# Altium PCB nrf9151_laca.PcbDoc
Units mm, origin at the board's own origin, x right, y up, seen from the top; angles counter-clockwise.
Board outline 17 x 22.5 mm, 4 copper layers (Top Layer, Mid-Layer 1, Mid-Layer 2, Bottom Layer), stack 1.514 mm thick; 12 components, 86 nets, 135 pads, 104 vias.
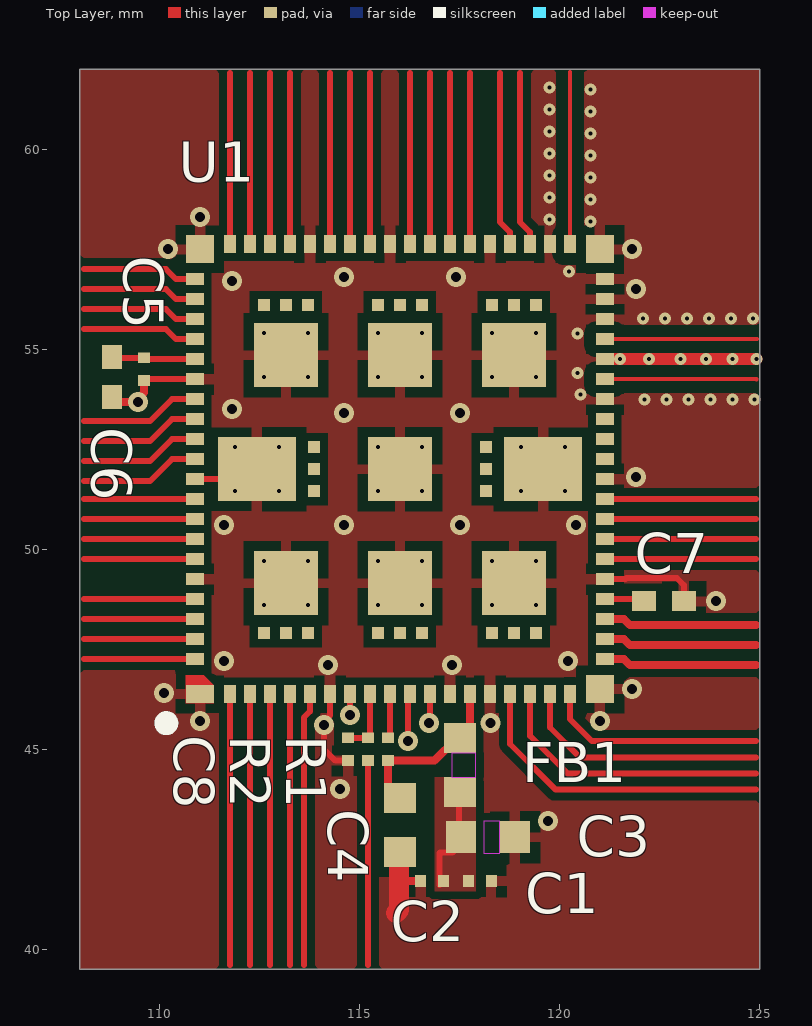
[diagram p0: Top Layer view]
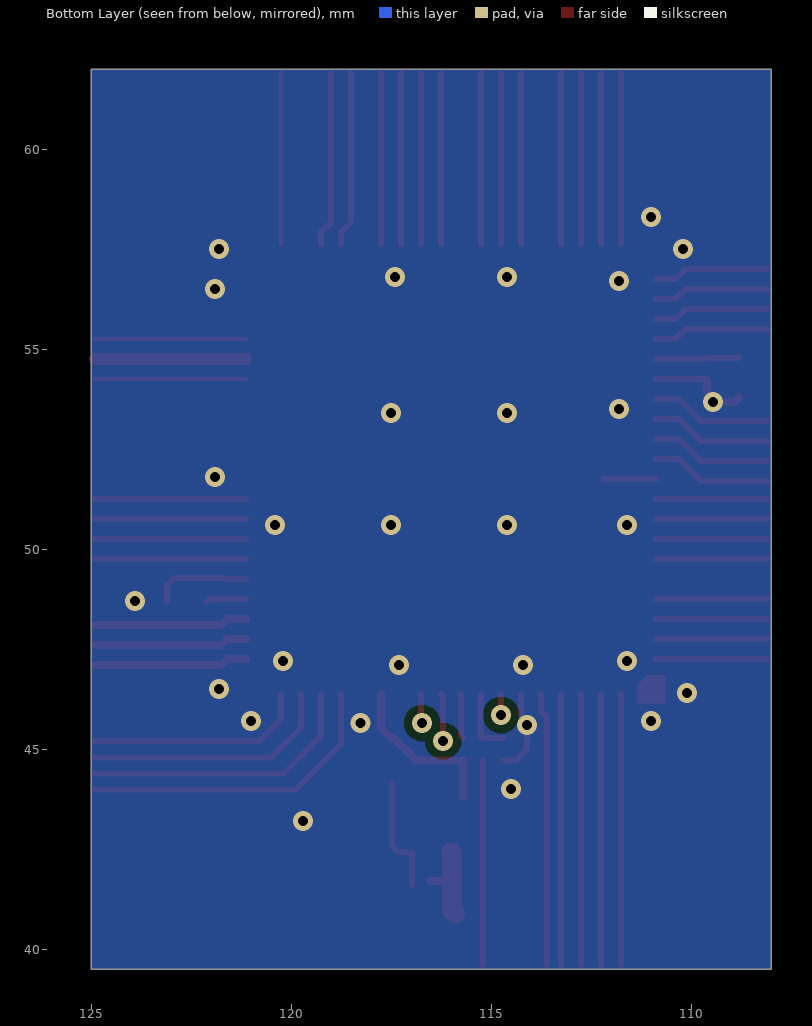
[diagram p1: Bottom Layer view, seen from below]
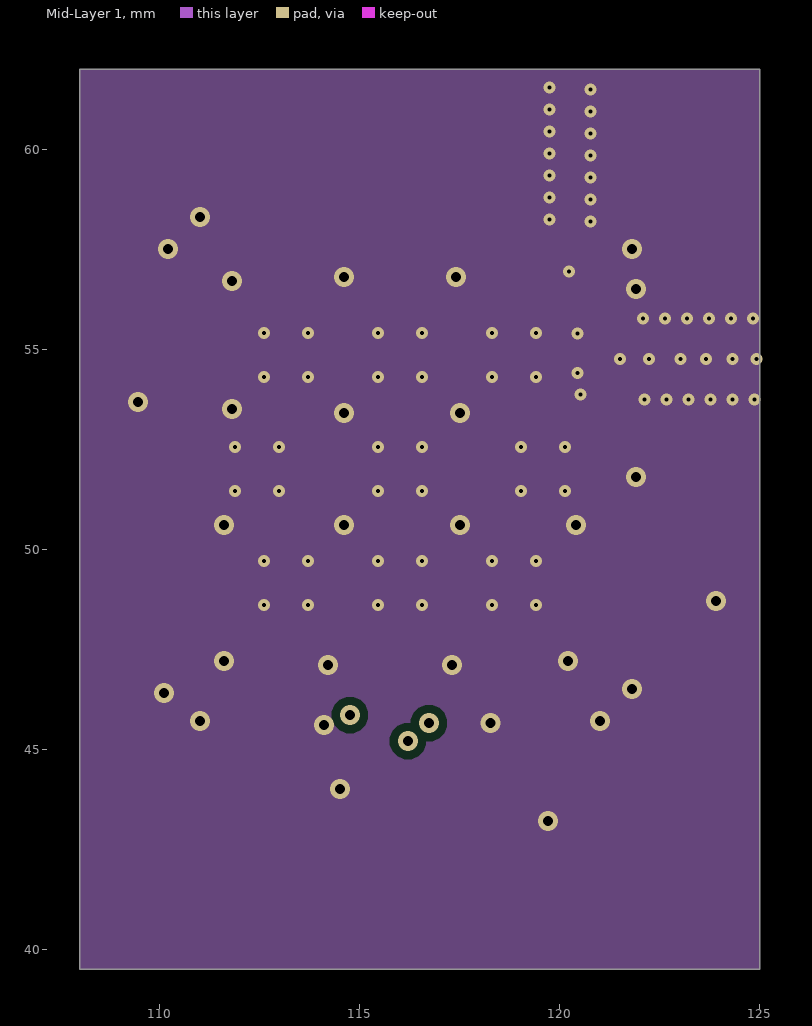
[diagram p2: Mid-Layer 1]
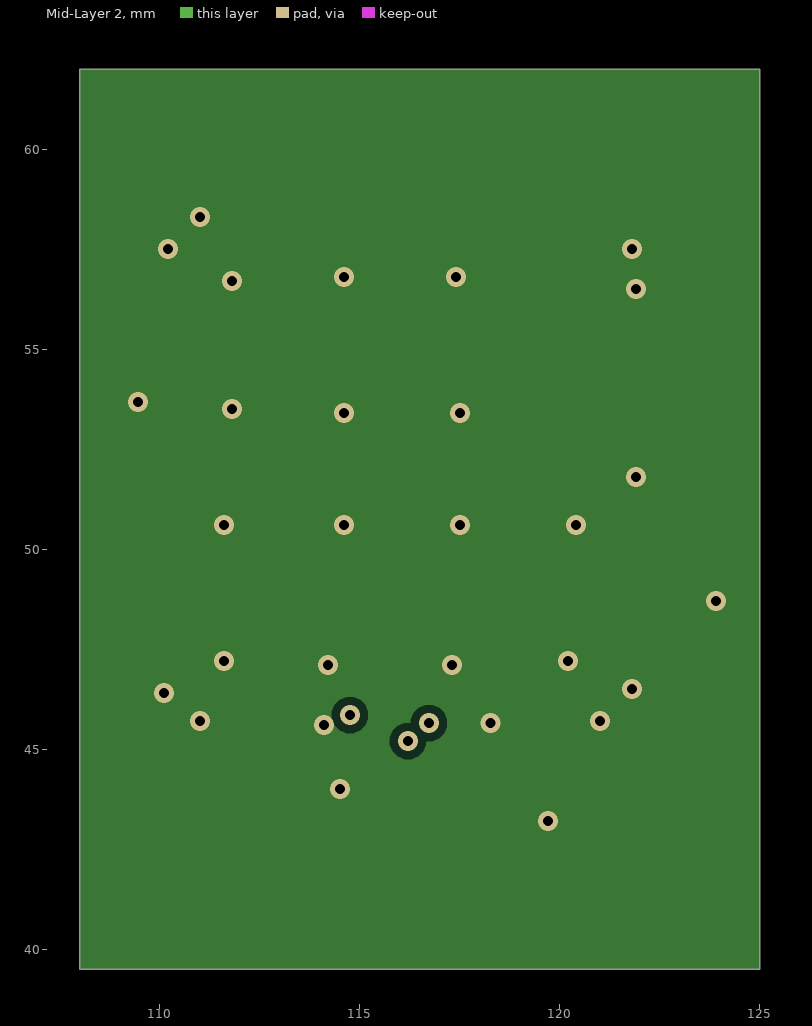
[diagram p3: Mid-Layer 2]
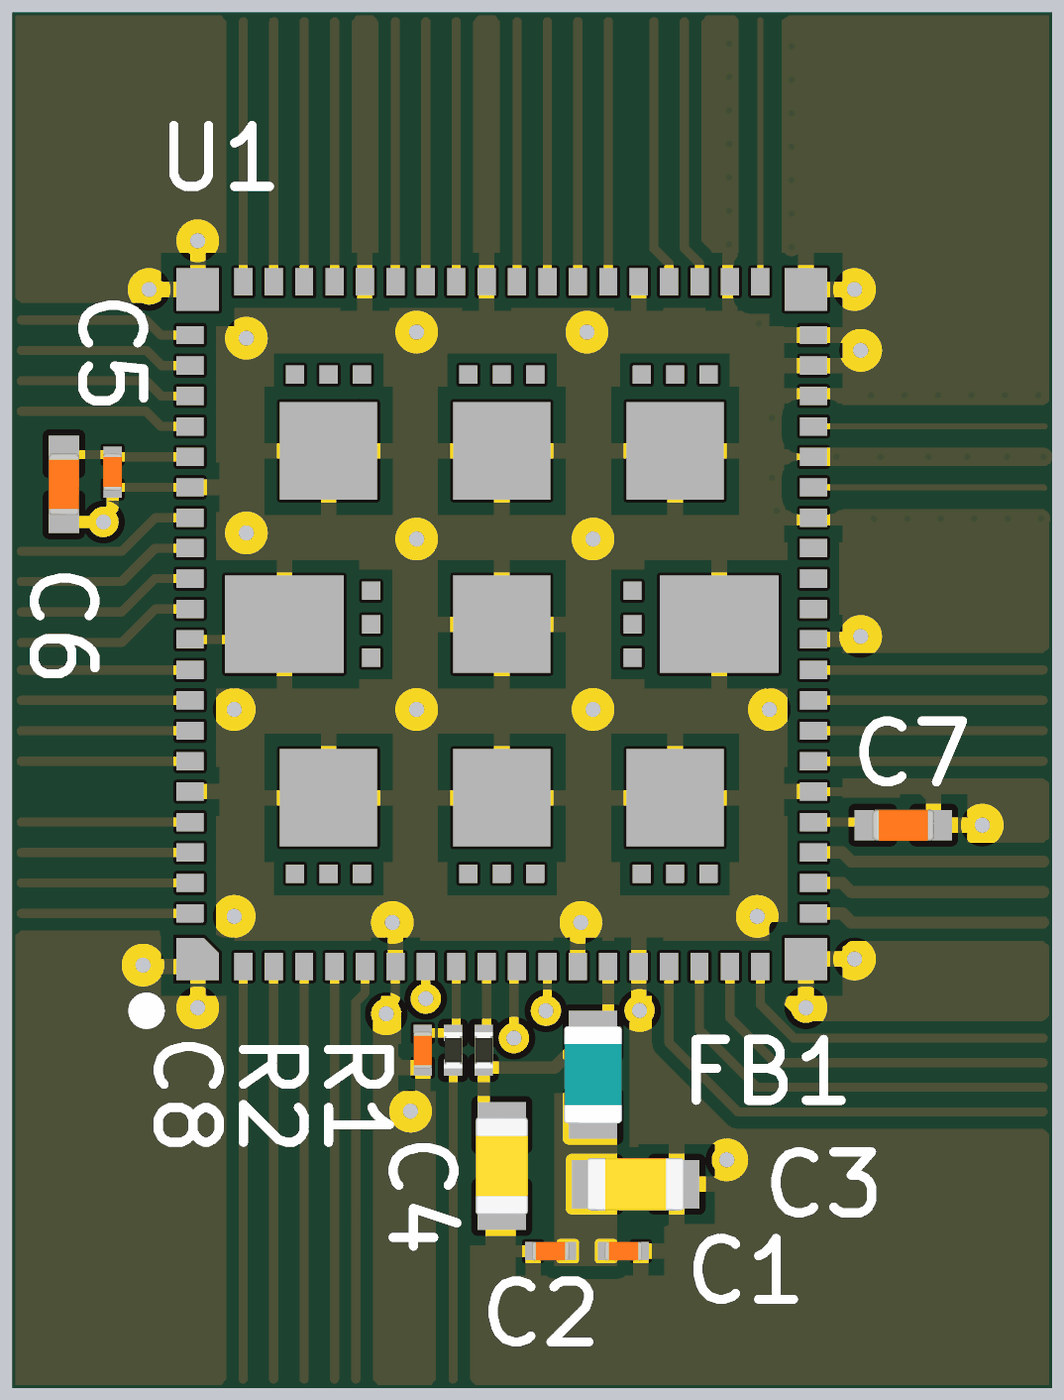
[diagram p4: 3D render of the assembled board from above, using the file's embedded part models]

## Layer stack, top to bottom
Top Solder: solder mask 0.05, Solder Resist Halogen-Free, Dk 3.5
Top Layer: signal copper 0.035
Dielectric1: prepreg 0.072, FR-4 Halogen-Free, Dk 4.18
Mid-Layer 1: signal copper 0.035
Dielectric2: core 1.23, FR-4 Halogen-Free, Dk 4.74
Mid-Layer 2: signal copper 0.035
Dielectric3: prepreg 0.072, FR-4 Halogen-Free, Dk 4.18
Bottom Layer: signal copper 0.035
Bottom Solder: solder mask 0.05, Solder Resist Halogen-Free, Dk 3.5

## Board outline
108,39.5 125,39.5 125,62 108,62

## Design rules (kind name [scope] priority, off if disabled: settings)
Clearance Clearance_1 [InNamedPolygon('Top_Layer-GND') or InNamedPolygon('Bottom_Layer-GND') or InNamedPolygon('Mid_Layer_1-GND') or InNamedPolygon('Mid_Layer_2-GND')] p1: gap=0.2 ignorepadtopadclearanceinfootprint=FALSE
Clearance GND_1 [InNet('GND')] p2: gap=0.15 ignorepadtopadclearanceinfootprint=FALSE except(0: Poly-Region)
Clearance [All] p3: gap=0.1 ignorepadtopadclearanceinfootprint=FALSE
MaxMinImpedance "Schematic Impedance Constraint_3" [InNetClass('50Ohm')] p1: minimum=50.00 maximum=50.00
PolygonConnect VDD_nRF [InNet('VDD_nRF')] p1: connectstyle=Direct reliefconductorwidth=0.254 reliefentries=4 polygonreliefangle="90 Angle" airgapwidth=0.254
PolygonConnect GND [IsPolygon vs IsVia] p2: connectstyle=Direct reliefconductorwidth=0.254 reliefentries=4 polygonreliefangle="90 Angle" airgapwidth=0.254
PolygonConnect [All] p3: connectstyle=Relief reliefconductorwidth=0.254 reliefentries=4 polygonreliefangle="90 Angle" airgapwidth=0.254
RoutingCorners [All] p1: cornerstyle=45-Degree minsetback=0.5 maxsetback=0.5
RoutingVias [All] p1: holewidth=0.25 width=0.5 viastyle="Through Hole" minholewidth=0.15 minwidth=0.3 maxholewidth=0.5 maxwidth=1
SolderMaskExpansion [All] p1: expansion=0.102 istentingtop=FALSE
Width RF_nets [InNetClass('50Ohm')] p1: maxlimit=0.254 minlimit=0.1 preferedwidth=0.254 toplayer_maxwidth=0.1 toplayer_prefwidth=0.1 bottomlayer_maxwidth=0.1 bottomlayer_prefwidth=0.1 impedanceprofiledriven=TRUE impedanceprofileid={14974C9B-F196-4B99-8CAC-E9FB9BDD5449} impedanceprofilevalue=50.000000 minimp=50.000000 maximp=50.000000 favimp=50.000000
Width "All tracks" [All] p2: maxlimit=1 minlimit=0.1 preferedwidth=0.15
29 further rules are at their usual default settings.

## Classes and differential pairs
net class 50Ohm: ANT AUX GPS

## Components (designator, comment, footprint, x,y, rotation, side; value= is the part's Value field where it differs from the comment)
C1 "1.0µF" CAPC0603X03L_C 118,41.7 r0 top
C2 "1.0µF" CAPC0603X03L_C 116.8,41.7 r180 top
C3 "10µF" CAPC1608X06L 118.2,42.8 r0 top
C4 "10µF" CAPC1608X06L 116,43.1 r270 top
C5 "100nF" CAPC0603X03L_C 109.6,54.5 r270 top
C6 "4.7µF" CAPC1005X04L 108.8,54.3 r270 top
C7 "4.7µF" CAPC1005X04L 122.6,48.7 r0 top
C8 "100nF" CAPC0603X03L_C 114.7,45 r270 top
FB1 "22R@100M/6A" INDC1608X06L 117.5,44.6 r90 top
R1 "10k" RESC0603X03L_C 115.7,45 r90 top
R2 "1k" RESC0603X03L_C 115.2,45 r90 top
U1 "nRF9151-LACAA0A" LGA50P1210X1110X130-113N 116,52 r0 top

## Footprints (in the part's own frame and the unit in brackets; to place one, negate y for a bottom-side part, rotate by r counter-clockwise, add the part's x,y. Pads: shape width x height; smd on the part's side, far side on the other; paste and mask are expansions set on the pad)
CAPC0603X03L_C [mm] "Chip Capacitor, 2-Leads, Body 0.6x0.3mm, IPC High Density"
  rect 0.27x0.3 smd mask+0.05: 1(-0.285,0) 2(0.285,0)
  body extent -0.3,-0.15 0.31,0.15, height 0.3
CAPC1005X04L [mm] "Chip Capacitor, 2-Leads, Body 1.0x0.5mm, IPC High Density"
  rect 0.6x0.5 smd: 1(-0.5,0) 2(0.5,0)
  body extent -0.51,-0.25 0.51,0.25, height 0.5
CAPC1608X06L [mm] "Chip Capacitor, 2-Leads, Body 1.6x0.8mm, IPC High Density"
  rect 0.75x0.8 smd: 1(-0.675,0) 2(0.675,0)
  body extent -0.8,-0.43 0.8,0.43, height 0.8
INDC1608X06L [mm] "Chip Inductor, 2-Leads, Body 1.6x0.8mm, IPC High Density"
  rect 0.75x0.8 smd: 1(-0.675,0) 2(0.675,0)
  body extent -0.8,-0.48 0.8,0.48, height 0.8
LGA50P1210X1110X130-113N [mm]
  rect 0.7x0.45 smd paste-2539.97 mask-5: 1(-5,-5.625)
  rect 0.3x0.45 smd mask+0.05: 2(-4.25,-5.625) 3(-3.75,-5.625) 4(-3.25,-5.625) 5(-2.75,-5.625) 6(-2.25,-5.625) 7(-1.75,-5.625) 8(-1.25,-5.625) 9(-0.75,-5.625) 10(-0.25,-5.625) 11(0.25,-5.625) 12(0.75,-5.625) 13(1.25,-5.625) 14(1.75,-5.625) 15(2.25,-5.625) 16(2.75,-5.625) 17(3.25,-5.625) 18(3.75,-5.625) 19(4.25,-5.625) 42(4.25,5.625) 43(3.75,5.625) 44(3.25,5.625) 45(2.75,5.625) 46(2.25,5.625) 47(1.75,5.625) 48(1.25,5.625) 49(0.75,5.625) 50(0.25,5.625) 51(-0.25,5.625) 52(-0.75,5.625) 53(-1.25,5.625) 54(-1.75,5.625) 55(-2.25,5.625) 56(-2.75,5.625) 57(-3.25,5.625) 58(-3.75,5.625) 59(-4.25,5.625)
  rect 0.7x0.7 smd mask+0.05: 20(5,-5.5) 41(5,5.5) 60(-5,5.5)
  rect 0.45x0.3 smd mask+0.05: 21(5.125,-4.75) 22(5.125,-4.25) 23(5.125,-3.75) 24(5.125,-3.25) 25(5.125,-2.75) 26(5.125,-2.25) 27(5.125,-1.75) 28(5.125,-1.25) 29(5.125,-0.75) 30(5.125,-0.25) 31(5.125,0.25) 32(5.125,0.75) 33(5.125,1.25) 34(5.125,1.75) 35(5.125,2.25) 36(5.125,2.75) 37(5.125,3.25) 38(5.125,3.75) 39(5.125,4.25) 40(5.125,4.75) 61(-5.125,4.75) 62(-5.125,4.25) 63(-5.125,3.75) 64(-5.125,3.25) 65(-5.125,2.75) 66(-5.125,2.25) 67(-5.125,1.75) 68(-5.125,1.25) 69(-5.125,0.75) 70(-5.125,0.25) 71(-5.125,-0.25) 72(-5.125,-0.75) 73(-5.125,-1.25) 74(-5.125,-1.75) 75(-5.125,-2.25) 76(-5.125,-2.75) 77(-5.125,-3.25) 78(-5.125,-3.75) 79(-5.125,-4.25) 80(-5.125,-4.75)
  rect 0.3x0.3 smd mask+0.05: 81(-3.4,-4.1) 82(-2.85,-4.1) 83(-2.3,-4.1) 84(-0.55,-4.1) 85(0,-4.1) 86(0.55,-4.1) 87(2.3,-4.1) 88(2.85,-4.1) 89(3.4,-4.1) 90(2.15,-0.55) 91(2.15,0) 92(2.15,0.55) 93(3.4,4.1) 94(2.85,4.1) 95(2.3,4.1) 96(0.55,4.1) 97(0,4.1) 98(-0.55,4.1) 99(-2.3,4.1) 100(-2.85,4.1) 101(-3.4,4.1) 102(-2.15,0.55) 103(-2.15,0) 104(-2.15,-0.55)
  rect 1.6x1.6 smd mask+0.05: 105(-2.85,-2.85) 106(0,-2.85) 107(2.85,-2.85) 109(2.85,2.85) 110(0,2.85) 111(-2.85,2.85) 113(0,0)
  rect 1.95x1.6 smd mask+0.05: 108(3.575,0) 112(-3.575,0)
  Top Layer region: -5.35,-5.15 -5.35,-5.85 -4.65,-5.85 -4.65,-5.4 -4.9,-5.15
  silkscreen extent -5.99,-6.5 -5.69,-6.2, body extent -5.6,-6.1 5.6,6.1, height 1.21
RESC0603X03L_C [mm] "Chip Resistor, 2-Leads, Body 0.6x0.3mm, IPC High Density"
  rect 0.27x0.3 smd: 1(-0.285,0) 2(0.285,0)
  body extent -0.3,-0.15 0.3,0.15, height 0.23

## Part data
C1 C2: library part C0201-1µ0-10V-X5R-GRM033R61A105ME15, "Capacitor, X5R, ±20%, 10V", Manufacturer=Murata, Manufacturer Part Number=GRM033R61A105ME15, Part number IPS=N.A., Part number NEMS=100200545, Supplier Part Number 1=490-13226-1-ND
C3 C4: library part C0603-10µ-10V-X6S-GRM188C81A106MA73, "Capacitor, Ceramic, 10µF 10V X6S 0603,±20%", Manufacturer=Murata, Manufacturer Part Number=GRM188C81A106MA73, Part number IPS=N.A., Part number NEMS=100200520, Supplier Part Number 1=490-7197-2-ND
C5: library part C0201-100n, "Capacitor, X5R, ±10%", Manufacturer=N.A., Part number IPS="00000001248, 00000002505", Part number NEMS=100200078, Part number Norautron=262071862
C6 C7: library part C0402-4µ7-10V-X5R, "Capacitor, X5R, 10V", Manufacturer=Murata, Manufacturer Part Number=GRM155R61A475MEAAD, Part number IPS=N.A., Part number NEMS=100200415, Supplier Part Number 1=490-14306-1-ND
C8: library part C0201-100n, "Capacitor, X5R, ±10%"
FB1: library part FB0603-22R@100MHz-6000mA, "Ferrite Bead, 22 Ohm @ 100MHz, 6000mA, 8 mOhm Max", Manufacturer=Murata, Manufacturer Part Number=BLM18SD220SN1D, Part number IPS=N.A., Supplier Part Number 1=490-15633-2-ND
R1: library part R0201-10k, "Resistor, ±1%, 0.05W", Manufacturer=N.A., Part number IPS=00000001255, Part number NEMS=100100065, Part number Norautron=26107101
R2: library part R0201-1k0, "Resistor, ±1%, 0.05W"
U1: "Low power System-in-Package with integrated LTE-M/NB-IoT modem and GPS", Manufacturer="Nordic Semiconductor", Part number IPS=N.A., Part number NEMS=102000328

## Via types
v1: diameter 0.3, hole 0.1, Top Layer to Mid-Layer 1, tented top, 36 vias
v2: diameter 0.3, hole 0.1, Top Layer to Mid-Layer 1, tented both sides, 36 vias
v3: diameter 0.5, hole 0.25, Top Layer to Bottom Layer, 32 vias

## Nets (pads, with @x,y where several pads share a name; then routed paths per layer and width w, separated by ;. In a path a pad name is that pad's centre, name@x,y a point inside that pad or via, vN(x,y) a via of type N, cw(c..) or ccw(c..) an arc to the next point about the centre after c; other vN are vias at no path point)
ANT: U1.35 | length 3.8
  Top Layer w0.1: U1.35 124.912,54.25 124.918,54.243
AUX: U1.37 | length 3.8
  Top Layer w0.1: U1.37 124.925,55.25
COEX0: U1.52 | length 4.3
  Top Layer w0.15: U1.52 115.25,61.9
COEX1: U1.53 | length 4.3
  Top Layer w0.15: U1.53 114.75,61.9
COEX2: U1.54 | length 4.3
  Top Layer w0.15: U1.54 114.25,61.9
DEC0: C7.1 U1.24 | length 1
  Top Layer w0.15: U1.24 122.05,48.75 C7.1
GND: C1.2 C2.2 C3.2 C4.2 C5.2 C6.2 C7.2 C8.2 U1.1 U1.7 U1.13 U1.15 U1.20 U1.25 U1.30 U1.34 U1.36 U1.38 U1.39 U1.40 U1.41 U1.43 U1.46 U1.51 U1.55 U1.60 U1.66 U1.71 U1.76 U1.105 U1.106 U1.107 U1.108 U1.109 U1.110 U1.111 U1.112 U1.113 | length 14.3
  Top Layer w0.15: C5.2@109.635,54.25 U1.66 ; U1.71 U1.112@112.175,51.75 ; U1.7 114.25,45.844 114.1,45.695 114.1,45 114.385,44.715 C8.2 ; U1.25 121.635,49.25 121.664,49.279 122.921,49.279 123.1,49.1 C7.2
  Top Layer w0.2: C6.2 108.92,53.68 v3(109.45,53.68) ; v3@109.45,53.682 109.45,53.761 109.6,53.911 C5.2 ; 115.98,41.7 C2.2
  Top Layer w0.3: U1.36 v1(124.907,54.75)
  Top Layer w0.5: 115.9,40.9 115.98,40.98 115.98,41.7 115.98,42.405 C4.2
  other v1: 122.117,53.737 122.667,53.737 123.217,53.737 123.767,53.737 124.317,53.737 124.867,53.737 120.518,53.862 120.443,54.407 121.501,54.75 122.227,54.75 123.016,54.75 123.653,54.75 124.307,54.75 120.441,55.391 122.072,55.763 122.622,55.763 123.172,55.763 123.722,55.763 124.272,55.763 124.822,55.763 120.229,56.941 120.763,58.195 119.737,58.241 120.763,58.745 119.737,58.791 120.763,59.295 119.737,59.341 120.763,59.845 119.737,59.891 120.763,60.395 119.737,60.441 120.763,60.945 119.737,60.991 120.763,61.495 119.737,61.541
  other v2: 112.6,48.6 113.7,48.6 115.45,48.6 116.55,48.6 118.3,48.6 119.4,48.6 112.6,49.7 113.7,49.7 115.45,49.7 116.55,49.7 118.3,49.7 119.4,49.7 111.875,51.45 112.975,51.45 115.45,51.45 116.55,51.45 119.025,51.45 120.125,51.45 111.875,52.55 112.975,52.55 115.45,52.55 116.55,52.55 119.025,52.55 120.125,52.55 112.6,54.3 113.7,54.3 115.45,54.3 116.55,54.3 118.3,54.3 119.4,54.3 112.6,55.4 113.7,55.4 115.45,55.4 116.55,55.4 118.3,55.4 119.4,55.4
  other v3: 119.7,43.2 114.5,44 114.1,45.6 118.265,45.655 111,45.7 121,45.7 110.1,46.4 121.8,46.5 114.2,47.1 117.3,47.1 111.6,47.2 120.2,47.2 123.9,48.7 111.6,50.6 114.6,50.6 117.5,50.6 120.4,50.6 121.9,51.8 114.6,53.4 117.5,53.4 111.8,53.5 121.9,56.5 111.8,56.7 114.6,56.8 117.4,56.8 110.2,57.5 121.8,57.5 111,58.3
GPS: U1.42 | length 4.3
  Top Layer w0.1: U1.42 120.25,61.925
MAGPIO0: U1.21 | length 3.8
  Top Layer w0.2: U1.21 121.6,47.25 121.75,47.1 124.9,47.1
MAGPIO1: U1.22 | length 3.8
  Top Layer w0.2: U1.22 121.6,47.75 121.75,47.6 124.9,47.6
MAGPIO2: U1.23 | length 3.8
  Top Layer w0.2: U1.23 121.6,48.25 121.75,48.1 124.9,48.1
MIPI_SCLK: U1.28 | length 3.8
  Top Layer w0.15: U1.28 124.9,50.75
MIPI_SDATA: U1.27 | length 3.8
  Top Layer w0.15: U1.27 124.9,50.25
MIPI_VIO: U1.29 | length 3.8
  Top Layer w0.15: U1.29 124.9,51.25
NetC4_1: C4.1 FB1.2 R1.1 U1.14 | length 4.1
  Top Layer w0.2: C4.1@115.697,43.815 115.7,43.818 R1.1 116.866,44.715 117.426,45.275 FB1.2 117.75,45.525 U1.14
NetC8_1: C8.1 R2.2 U1.9 | length 1.6
  Top Layer w0.15: C8.1 R2.2 115.25,45.335 U1.9
NetR1_2: R1.2 U1.10 | length 1.1
  Top Layer w0.15: R1.2 115.75,45.335 U1.10
NetU1_31: U1.31
NetU1_32: U1.32
NetU1_33: U1.33
NetU1_81: U1.81
NetU1_82: U1.82
NetU1_83: U1.83
NetU1_84: U1.84
NetU1_85: U1.85
NetU1_86: U1.86
NetU1_87: U1.87
NetU1_88: U1.88
NetU1_89: U1.89
NetU1_90: U1.90
NetU1_91: U1.91
NetU1_92: U1.92
NetU1_93: U1.93
NetU1_94: U1.94
NetU1_95: U1.95
NetU1_96: U1.96
NetU1_97: U1.97
NetU1_98: U1.98
NetU1_99: U1.99
NetU1_100: U1.100
NetU1_101: U1.101
NetU1_102: U1.102
NetU1_103: U1.103
NetU1_104: U1.104
nRESET: R2.1 | length 5.1
  Top Layer w0.15: 115.2,39.6 R2.1
P0.00: U1.56 | length 4.3
  Top Layer w0.15: U1.56 113.25,61.9
P0.01: U1.57 | length 4.3
  Top Layer w0.15: U1.57 112.75,61.9
P0.02: U1.58 | length 4.3
  Top Layer w0.15: U1.58 112.25,61.9
P0.03: U1.59 | length 4.3
  Top Layer w0.15: U1.59 111.75,61.9
P0.04: U1.61 | length 2.9
  Top Layer w0.15: 108.1,57 110.15,57 110.4,56.75 U1.61
P0.05: U1.62 | length 2.9
  Top Layer w0.15: 108.1,56.5 110.15,56.5 110.4,56.25 U1.62
P0.06: U1.63 | length 2.9
  Top Layer w0.15: 108.1,56 110.15,56 110.4,55.75 U1.63
P0.07: U1.64 | length 2.9
  Top Layer w0.15: 108.1,55.5 110.15,55.5 110.4,55.25 U1.64
P0.08: U1.67 | length 3
  Top Layer w0.15: 108.1,53.2 109.75,53.2 110.3,53.75 U1.67
P0.09: U1.68 | length 3
  Top Layer w0.15: 108.1,52.7 109.75,52.7 110.3,53.25 U1.68
P0.10: U1.69 | length 3
  Top Layer w0.15: 108.1,52.2 109.75,52.2 110.3,52.75 U1.69
P0.11: U1.70 | length 3
  Top Layer w0.15: 108.1,51.7 109.75,51.7 110.3,52.25 U1.70
P0.12: U1.72 | length 2.8
  Top Layer w0.15: 108.1,51.25 U1.72
P0.13/AIN0: U1.73 | length 2.8
  Top Layer w0.15: 108.1,50.75 U1.73
P0.14/AIN1: U1.74 | length 2.8
  Top Layer w0.15: 108.1,50.25 U1.74
P0.15/AIN2: U1.75 | length 2.8
  Top Layer w0.15: 108.1,49.75 U1.75
P0.16/AIN3: U1.77 | length 2.8
  Top Layer w0.15: 108.1,48.75 U1.77
P0.17/AIN4: U1.78 | length 2.8
  Top Layer w0.15: 108.1,48.25 U1.78
P0.18/AIN5: U1.79 | length 2.8
  Top Layer w0.15: 108.1,47.75 U1.79
P0.19/AIN6: U1.80 | length 2.8
  Top Layer w0.15: 108.1,47.25 U1.80
P0.20/AIN7: U1.2 | length 6.8
  Top Layer w0.15: 111.75,39.6 U1.2
P0.21/TRACECLK: U1.5 | length 6.8
  Top Layer w0.15: 113.25,39.6 U1.5
P0.22/TRACEDATA[0]: U1.6 | length 6.8
  Top Layer w0.15: 113.6,39.6 113.6,45.798 113.75,45.948 U1.6
P0.23/TRACEDATA[1]: U1.8 | length 0.5
  Top Layer w0.15: v3(114.75,45.85) U1.8
P0.24/TRACEDATA[2]: U1.11 | length 1.2
  Top Layer w0.15: v3(116.2,45.2) 116.2,46.325 U1.11
P0.24/TRACEDATA[3]: U1.12 | length 0.8
  Top Layer w0.15: v3(116.725,45.65) 116.75,45.65 U1.12
  Bottom Layer w0.15: v3@116.725,45.625 v3(116.725,45.65)
P0.26: U1.44 | length 4.4
  Top Layer w0.15: 119,61.9 119,58.175 119.25,57.925 U1.44
P0.27: U1.45 | length 4.4
  Top Layer w0.15: 118.5,61.9 118.5,58.175 118.75,57.925 U1.45
P0.28: U1.47 | length 4.3
  Top Layer w0.15: U1.47 117.75,61.9
P0.29: U1.48 | length 4.3
  Top Layer w0.15: U1.48 117.25,61.9
P0.30: U1.49 | length 4.3
  Top Layer w0.15: U1.49 116.75,61.9
P0.31: U1.50 | length 4.3
  Top Layer w0.15: U1.50 116.25,61.9
SIM_1V8: U1.19 | length 5.5
  Top Layer w0.15: U1.19 120.25,45.75 120.8,45.2 124.9,45.2
SIM_CLK: U1.18 | length 6.3
  Top Layer w0.15: U1.18 119.75,45.543 120.496,44.796 124.9,44.796
SIM_DET: U1.26 | length 3.8
  Top Layer w0.15: U1.26 124.9,49.75
SIM_IO: U1.17 | length 7.1
  Top Layer w0.15: U1.17 119.25,45.336 120.193,44.392 124.9,44.392
SIM_RST: U1.16 | length 7.9
  Top Layer w0.15: U1.16 118.75,45.129 119.89,43.988 124.9,43.988
SWDCLK: U1.3 | length 6.8
  Top Layer w0.15: 112.25,39.6 U1.3
SWDIO: U1.4 | length 6.8
  Top Layer w0.15: 112.75,39.6 U1.4
VDD_GPIO: C5.1 C6.1 U1.65 | length 2.1
  Top Layer w0.15: C6.1 108.815,54.785 C5.1 109.635,54.75 U1.65
VDD_nRF: C1.1 C2.1 C3.1 FB1.1 | length 2.9
  Top Layer w0.15: C2.1@116.985,41.6 116.985,42 116.985,42.405 116.99,42.41 116.998,42.418 117.318,42.418 117.475,42.575 117.475,43.18 FB1.1@117.475,44.156

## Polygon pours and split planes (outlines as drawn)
GND on Top Layer "Top_Layer-GND" (solid, remove dead copper, pour order 8): 108,62 125,62 125,39.5 108,39.5
VDD_nRF on Top Layer "VDD_nRF" (solid, remove dead copper, pour order 6): 117.9,44.3 116.863,44.3 116.863,41.45 117.9,41.45
GND on Mid-Layer 2 "Mid_Layer_2-GND" (solid, remove dead copper, pour order 5): 108,62 125,62 125,39.5 108,39.5
GND on Bottom Layer "Bottom_Layer-GND" (solid, remove dead copper, pour order 9): 108,62 125,62 125,39.5 108,39.5
GND on Mid-Layer 1 "Mid_Layer_1-GND" (solid, remove dead copper, pour order 10): 108,62 125,62 125,39.5 108,39.5

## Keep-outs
Top Layer:
  region: 117.9,44.3 117.9,44.9 117.3,44.9 117.3,44.3
  rectangle: 118.1,42.403 118.5,43.203

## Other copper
Top Layer:
  pour cut-out: 120.25,62.28 120.261,62.278 120.365,62.257 120.403,62.241 120.477,62.192 120.501,62.176 120.558,62.091 120.566,62.078 120.582,62.04 120.591,61.994 120.605,61.925 120.605,58.068 120.613,58.063 120.678,57.965 120.701,57.85 120.701,57.4 120.678,57.285 120.613,57.187 120.515,57.122 120.4,57.099 120.1,57.099 119.985,57.122 119.887,57.187 119.822,57.285 119.799,57.4 119.799,57.85 119.822,57.965 119.887,58.063 119.895,58.068 119.895,61.925 119.918,62.04 119.934,62.078 119.983,62.152 119.999,62.176 120.084,62.233 120.097,62.241 120.135,62.257 120.187,62.267
  pour cut-out: 121.465,55.678 121.563,55.613 121.568,55.605 124.925,55.605 125.04,55.582 125.078,55.566 125.152,55.517 125.176,55.501 125.233,55.416 125.241,55.403 125.257,55.365 125.267,55.313 125.28,55.25 125.278,55.239 125.257,55.135 125.241,55.097 125.192,55.023 125.176,54.999 125.091,54.942 125.078,54.934 125.04,54.918 124.994,54.909 124.925,54.895 121.568,54.895 121.563,54.887 121.465,54.822 121.35,54.799 120.9,54.799 120.785,54.822 120.687,54.887 120.622,54.985 120.599,55.1 120.599,55.4 120.622,55.515 120.687,55.613 120.785,55.678 120.9,55.701 121.35,55.701
  pour cut-out: 121.465,54.678 121.563,54.613 121.568,54.605 124.912,54.605 124.946,54.598 125.027,54.582 125.065,54.566 125.102,54.542 125.163,54.501 125.169,54.494 125.234,54.397 125.25,54.358 125.262,54.297 125.273,54.243 125.262,54.189 125.25,54.128 125.234,54.09 125.21,54.053 125.169,53.992 125.109,53.952 125.072,53.927 125.033,53.911 124.972,53.899 124.918,53.889 124.885,53.895 121.568,53.895 121.563,53.887 121.465,53.822 121.35,53.799 120.9,53.799 120.785,53.822 120.687,53.887 120.622,53.985 120.599,54.1 120.599,54.4 120.622,54.515 120.687,54.613 120.785,54.678 120.9,54.701 121.35,54.701

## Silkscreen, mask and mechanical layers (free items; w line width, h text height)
Board:
  the board outline again, w0.1

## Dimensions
125,39.5 to 125,62 on Dimentions
108,39.5 to 125,39.5 on Dimentions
